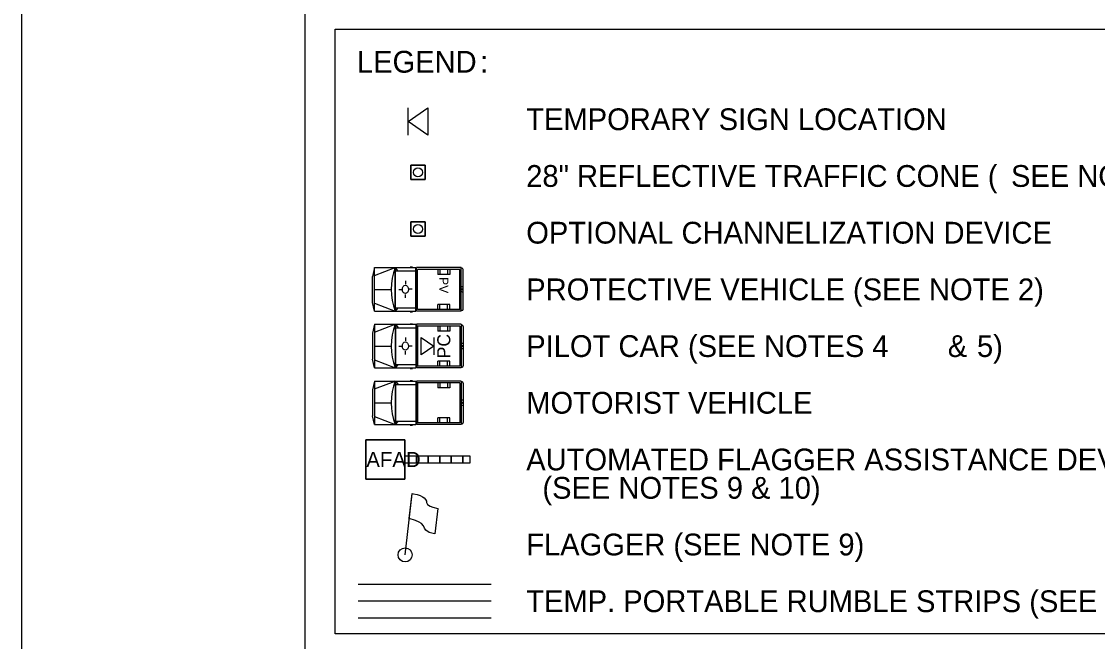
# Model space of a CAD drawing. Extents: x 99999.1 to 100095.7, y 99995 to 100010.7.
# Drawn here: x 99999.062 to 100002.622, y 100001.151 to 100003.2 of the extents above; entities that cross this region are included whole.
import ezdxf

# ---------------------------------------------------------------- set-up
doc = ezdxf.new("R2010")
doc.units = 0
for name, color, linetype in [('SH_GI_PlotLimits', 7, 'Continuous'), ('SH_GI_SheetBorder', 7, 'Continuous'), ('TR_WZ_AFAD', 7, 'Continuous'), ('TR_WZ_FlaggingStation', 7, 'Continuous'), ('TR_WZ_MotoristVehicle', 7, 'Continuous'), ('TR_WZ_PortableSignMountBlk-Org', 7, 'Continuous'), ('TR_WZ_PortableSignMountBlk-Wht', 7, 'Continuous'), ('TR_WZ_ProtectiveVehicle', 7, 'Continuous'), ('TR_WZ_TrafficCone', 7, 'Continuous'), ('TR_WZ_WorkZoneDetails', 7, 'Continuous'), ('TR_WZ_WorkZoneTextCurrent', 7, 'Continuous')]:
    doc.layers.add(name, color=color, linetype=linetype)

msp = doc.modelspace()

# ---------------------------------------------------------------- linework, layer by layer
at = {"layer": 'SH_GI_PlotLimits'}
msp.add_lwpolyline([(99999.0625, 99999.6875), (100016.0625, 99999.6875), (100016.0625, 100010.6875), (99999.0625, 100010.6875)], close=True, dxfattribs=at)
at = {"layer": 'SH_GI_SheetBorder'}
msp.add_line((100000, 100010.375), (100000, 100000), dxfattribs=at)
at = {"layer": 'TR_WZ_AFAD'}
for p, q in [((100000.2009, 100001.6877), (100000.2009, 100001.8173)), ((100000.2009, 100001.8173), (100000.3305, 100001.8173)), ((100000.3305, 100001.8173), (100000.2009, 100001.8173)), ((100000.2009, 100001.8173), (100000.2009, 100001.6877)), ((100000.3305, 100001.8173), (100000.3305, 100001.6877)), ((100000.3305, 100001.7573), (100000.3305, 100001.8173)), ((100000.3689, 100001.7633), (100000.3305, 100001.7633)), ((100000.3305, 100001.7633), (100000.3305, 100001.7573)), ((100000.3305, 100001.7573), (100000.3305, 100001.7525)), ((100000.4073, 100001.7633), (100000.3689, 100001.7633)), ((100000.4457, 100001.7633), (100000.4073, 100001.7633)), ((100000.4073, 100001.7525), (100000.4073, 100001.7633)), ((100000.4073, 100001.7417), (100000.4073, 100001.7525)), ((100000.4841, 100001.7633), (100000.4457, 100001.7633)), ((100000.4457, 100001.7633), (100000.4457, 100001.7525)), ((100000.4457, 100001.7525), (100000.4457, 100001.7417)), ((100000.5225, 100001.7633), (100000.4841, 100001.7633)), ((100000.4841, 100001.7525), (100000.4841, 100001.7633)), ((100000.4841, 100001.7417), (100000.4841, 100001.7525)), ((100000.5225, 100001.7633), (100000.5225, 100001.7525)), ((100000.5225, 100001.7525), (100000.5225, 100001.7417)), ((100000.3689, 100001.7417), (100000.4073, 100001.7417)), ((100000.4073, 100001.7417), (100000.4457, 100001.7417)), ((100000.4457, 100001.7417), (100000.4841, 100001.7417)), ((100000.4841, 100001.7417), (100000.5225, 100001.7417)), ((100000.5225, 100001.7417), (100000.5465, 100001.7417)), ((100000.3305, 100001.6877), (100000.2009, 100001.6877)), ((100000.2009, 100001.6877), (100000.3305, 100001.6877))]:
    msp.add_line(p, q, dxfattribs=at)
for points in [[(100000.3305, 100001.7417), (100000.5465, 100001.7417), (100000.5465, 100001.7633), (100000.3305, 100001.7633)], [(100000.3305, 100001.6877), (100000.3305, 100001.7477), (100000.3305, 100001.7573)], [(100000.3305, 100001.7525), (100000.3305, 100001.7477), (100000.3305, 100001.7417), (100000.3689, 100001.7417)], [(100000.3689, 100001.7417), (100000.3689, 100001.7525), (100000.3689, 100001.7633)], [(100000.3689, 100001.7633), (100000.3689, 100001.7525), (100000.3689, 100001.7417)], [(100000.4073, 100001.7633), (100000.4073, 100001.7525), (100000.4073, 100001.7417)], [(100000.4457, 100001.7417), (100000.4457, 100001.7525), (100000.4457, 100001.7633)], [(100000.4841, 100001.7633), (100000.4841, 100001.7525), (100000.4841, 100001.7417)], [(100000.5225, 100001.7417), (100000.5225, 100001.7525), (100000.5225, 100001.7633)], [(100000.5465, 100001.7417), (100000.5465, 100001.7633), (100000.5225, 100001.7633)]]:
    msp.add_lwpolyline(points, dxfattribs=at)
at = {"layer": 'TR_WZ_FlaggingStation'}
for p, q in [((100000.3314, 100001.4372), (100000.3545, 100001.6394)), ((100000.3451, 100001.5573), (100000.3545, 100001.6397)), ((100000.4394, 100001.5908), (100000.4299, 100001.5065)), ((100000.3451, 100001.5573), (100000.3451, 100001.5573))]:
    msp.add_line(p, q, dxfattribs=at)
for points in [[(100000.3545, 100001.6397), (100000.3586, 100001.6387), (100000.3715, 100001.6363), (100000.3814, 100001.6333), (100000.3884, 100001.6289), (100000.3945, 100001.6255), (100000.3986, 100001.6206), (100000.4017, 100001.6149), (100000.4021, 100001.6105), (100000.4059, 100001.6038), (100000.4137, 100001.5985), (100000.4226, 100001.5947), (100000.4394, 100001.5908)], [(100000.4299, 100001.5065), (100000.424, 100001.5075), (100000.4112, 100001.5108), (100000.4, 100001.5184), (100000.3953, 100001.526), (100000.3925, 100001.5334), (100000.3859, 100001.5412), (100000.378, 100001.5457), (100000.3655, 100001.5508), (100000.3451, 100001.5573)]]:
    msp.add_lwpolyline(points, dxfattribs=at)
msp.add_circle((100000.3314, 100001.4372), 0.0234, dxfattribs=at)
at = {"layer": 'TR_WZ_MotoristVehicle'}
for p, q in [((100000.2305, 100002.1994), (100000.2239, 100002.1704)), ((100000.2305, 100002.1994), (100000.2305, 100002.0554)), ((100000.2305, 100002.1994), (100000.3665, 100002.1994)), ((100000.2305, 100002.1731), (100000.2985, 100002.1994)), ((100000.2985, 100002.1994), (100000.2985, 100002.0554)), ((100000.2998, 100002.1994), (100000.2998, 100002.0554)), ((100000.2998, 100002.1994), (100000.3084, 100002.1883)), ((100000.2998, 100002.1883), (100000.3665, 100002.1883)), ((100000.348, 100002.2015), (100000.3562, 100002.2015)), ((100000.3665, 100002.1994), (100000.3665, 100002.0554)), ((100000.5166, 100002.1994), (100000.3685, 100002.1994)), ((100000.3685, 100002.1994), (100000.3685, 100002.0554)), ((100000.5124, 100002.1937), (100000.3727, 100002.1937)), ((100000.3727, 100002.1937), (100000.3727, 100002.0612)), ((100000.4395, 100002.1937), (100000.4395, 100002.1771)), ((100000.4791, 100002.1771), (100000.4395, 100002.1771)), ((100000.4467, 100002.1937), (100000.4467, 100002.1771)), ((100000.4711, 100002.1937), (100000.4711, 100002.1771)), ((100000.4791, 100002.1937), (100000.4791, 100002.1771)), ((100000.5124, 100002.1937), (100000.5124, 100002.0612)), ((100000.5166, 100002.1994), (100000.5166, 100002.0554)), ((100000.5204, 100002.1971), (100000.5171, 100002.1971)), ((100000.5171, 100002.1971), (100000.5171, 100002.0578)), ((100000.5236, 100002.1927), (100000.5236, 100002.0622)), ((100000.2239, 100002.1704), (100000.2239, 100002.0845)), ((100000.3324, 100002.156), (100000.3324, 100002.1444)), ((100000.5236, 100002.1376), (100000.5171, 100002.1349)), ((100000.2305, 100002.1274), (100000.2852, 100002.1274)), ((100000.3107, 100002.1275), (100000.3198, 100002.1275)), ((100000.3329, 100002.0997), (100000.3327, 100002.1106)), ((100000.3426, 100002.1272), (100000.3426, 100002.1272)), ((100000.3546, 100002.1269), (100000.3439, 100002.1272)), ((100000.5236, 100002.1173), (100000.5171, 100002.12)), ((100000.5218, 100002.1274), (100000.5189, 100002.1274)), ((100000.5204, 100002.1295), (100000.5204, 100002.1254)), ((100000.2305, 100002.0554), (100000.2239, 100002.0845)), ((100000.2305, 100002.0818), (100000.2985, 100002.0554)), ((100000.2998, 100002.0666), (100000.3665, 100002.0666)), ((100000.3069, 100002.0666), (100000.2998, 100002.0554)), ((100000.4395, 100002.0612), (100000.4395, 100002.0777)), ((100000.4791, 100002.0777), (100000.4395, 100002.0777)), ((100000.4467, 100002.0612), (100000.4467, 100002.0777)), ((100000.4711, 100002.0612), (100000.4711, 100002.0777)), ((100000.4791, 100002.0612), (100000.4791, 100002.0777)), ((100000.2305, 100002.0554), (100000.3665, 100002.0554)), ((100000.348, 100002.0534), (100000.3562, 100002.0534)), ((100000.5166, 100002.0554), (100000.3685, 100002.0554)), ((100000.5124, 100002.0612), (100000.3727, 100002.0612)), ((100000.5204, 100002.0578), (100000.5171, 100002.0578)), ((100000.2305, 100002.012), (100000.2239, 100001.9829)), ((100000.2305, 100002.012), (100000.2305, 100001.868)), ((100000.2305, 100002.012), (100000.3665, 100002.012)), ((100000.2305, 100001.9856), (100000.2985, 100002.012)), ((100000.2985, 100002.012), (100000.2985, 100001.868)), ((100000.2998, 100002.012), (100000.2998, 100001.868)), ((100000.2998, 100002.012), (100000.3084, 100002.0008)), ((100000.2998, 100002.0008), (100000.3665, 100002.0008)), ((100000.348, 100002.014), (100000.3562, 100002.014)), ((100000.3665, 100002.012), (100000.3665, 100001.868)), ((100000.5166, 100002.012), (100000.3685, 100002.012)), ((100000.3685, 100002.012), (100000.3685, 100001.868)), ((100000.5124, 100002.0062), (100000.3727, 100002.0062)), ((100000.3727, 100002.0062), (100000.3727, 100001.8737)), ((100000.4395, 100002.0062), (100000.4395, 100001.9897)), ((100000.4467, 100002.0062), (100000.4467, 100001.9897)), ((100000.4711, 100002.0062), (100000.4711, 100001.9897)), ((100000.4791, 100002.0062), (100000.4791, 100001.9897)), ((100000.5124, 100002.0062), (100000.5124, 100001.8737)), ((100000.5166, 100002.012), (100000.5166, 100001.868)), ((100000.5204, 100002.0096), (100000.5171, 100002.0096)), ((100000.5171, 100002.0096), (100000.5171, 100001.8704)), ((100000.5236, 100002.0052), (100000.5236, 100001.8747)), ((100000.2239, 100001.9829), (100000.2239, 100001.8971)), ((100000.4791, 100001.9897), (100000.4395, 100001.9897)), ((100000.2305, 100001.94), (100000.2852, 100001.94)), ((100000.5236, 100001.9501), (100000.5171, 100001.9474)), ((100000.5236, 100001.9298), (100000.5171, 100001.9325)), ((100000.5218, 100001.94), (100000.5189, 100001.94)), ((100000.5204, 100001.942), (100000.5204, 100001.938)), ((100000.2305, 100001.868), (100000.2239, 100001.8971)), ((100000.2305, 100001.8944), (100000.2985, 100001.868)), ((100000.4395, 100001.8737), (100000.4395, 100001.8903)), ((100000.4791, 100001.8903), (100000.4395, 100001.8903)), ((100000.4467, 100001.8737), (100000.4467, 100001.8903)), ((100000.4711, 100001.8737), (100000.4711, 100001.8903)), ((100000.4791, 100001.8737), (100000.4791, 100001.8903)), ((100000.2305, 100001.868), (100000.3665, 100001.868)), ((100000.2998, 100001.8791), (100000.3665, 100001.8791)), ((100000.3069, 100001.8791), (100000.2998, 100001.868)), ((100000.348, 100001.866), (100000.3562, 100001.866)), ((100000.5166, 100001.868), (100000.3685, 100001.868)), ((100000.5124, 100001.8737), (100000.3727, 100001.8737)), ((100000.5204, 100001.8704), (100000.5171, 100001.8704))]:
    msp.add_line(p, q, dxfattribs=at)
for centre, major_axis, start_param, end_param in [((100000.3957, 100002.1274), (0, -0.1511), 4.215667, 5.208926), ((100000.5204, 100002.1927), (0, 0.00439), 4.712389, 6.283185), ((100000.5204, 100002.0622), (0, -0.00439), 0, 1.570796), ((100000.3957, 100001.94), (0, -0.1511), 4.215667, 5.208926), ((100000.5204, 100002.0052), (0, 0.00439), 4.712389, 6.283185), ((100000.5204, 100001.8747), (0, -0.00439), 0, 1.570796)]:
    msp.add_ellipse(centre, major_axis=major_axis, ratio=0.73155, start_param=start_param, end_param=end_param, dxfattribs=at)
for centre, major_axis in [((100000.3324, 100002.1274), (0, 0.0139)), ((100000.5204, 100002.1274), (0, 0.00203)), ((100000.5204, 100001.94), (0, 0.00203))]:
    msp.add_ellipse(centre, major_axis=major_axis, ratio=0.73155, dxfattribs=at)
at = {"layer": 'TR_WZ_PortableSignMountBlk-Org'}
msp.add_line((100000.3414, 100002.8247), (100000.3414, 100002.9147), dxfattribs=at)
msp.add_lwpolyline([(100000.3414, 100002.8696), (100000.406, 100002.9147), (100000.406, 100002.8247)], close=True, dxfattribs=at)
at = {"layer": 'TR_WZ_PortableSignMountBlk-Wht'}
msp.add_line((100000.4259, 100002.1562), (100000.4259, 100002.0986), dxfattribs=at)
msp.add_lwpolyline([(100000.4259, 100002.1274), (100000.3845, 100002.0986), (100000.3845, 100002.1562)], close=True, dxfattribs=at)
at = {"layer": 'TR_WZ_ProtectiveVehicle'}
for p, q in [((100000.2305, 100002.3869), (100000.2239, 100002.3578)), ((100000.2305, 100002.2429), (100000.2305, 100002.3869)), ((100000.2305, 100002.3869), (100000.3665, 100002.3869)), ((100000.2305, 100002.3605), (100000.2985, 100002.3869)), ((100000.2985, 100002.2429), (100000.2985, 100002.3869)), ((100000.2998, 100002.2429), (100000.2998, 100002.3869)), ((100000.3069, 100002.3757), (100000.2998, 100002.3869)), ((100000.348, 100002.3889), (100000.3562, 100002.3889)), ((100000.3665, 100002.2429), (100000.3665, 100002.3869)), ((100000.5166, 100002.3869), (100000.3685, 100002.3869)), ((100000.3685, 100002.2429), (100000.3685, 100002.3869)), ((100000.5166, 100002.2429), (100000.5166, 100002.3869)), ((100000.5204, 100002.3845), (100000.5171, 100002.3845)), ((100000.5171, 100002.2453), (100000.5171, 100002.3845)), ((100000.2239, 100002.272), (100000.2239, 100002.3578)), ((100000.2998, 100002.3757), (100000.3665, 100002.3757)), ((100000.5124, 100002.3811), (100000.3727, 100002.3811)), ((100000.3727, 100002.2486), (100000.3727, 100002.3811)), ((100000.4395, 100002.3811), (100000.4395, 100002.3646)), ((100000.4791, 100002.3646), (100000.4395, 100002.3646)), ((100000.4467, 100002.3811), (100000.4467, 100002.3646)), ((100000.4711, 100002.3811), (100000.4711, 100002.3646)), ((100000.4791, 100002.3811), (100000.4791, 100002.3646)), ((100000.5124, 100002.2486), (100000.5124, 100002.3811)), ((100000.5236, 100002.2497), (100000.5236, 100002.3801)), ((100000.2305, 100002.3149), (100000.2852, 100002.3149)), ((100000.3107, 100002.3148), (100000.3198, 100002.3148)), ((100000.3329, 100002.3426), (100000.3327, 100002.3318)), ((100000.3426, 100002.3151), (100000.3426, 100002.3151)), ((100000.3546, 100002.3154), (100000.3439, 100002.3152)), ((100000.5236, 100002.325), (100000.5171, 100002.3223)), ((100000.5218, 100002.3149), (100000.5189, 100002.3149)), ((100000.5204, 100002.3129), (100000.5204, 100002.3169)), ((100000.3324, 100002.2864), (100000.3324, 100002.298)), ((100000.5236, 100002.3048), (100000.5171, 100002.3075)), ((100000.2305, 100002.2429), (100000.2239, 100002.272)), ((100000.2305, 100002.2693), (100000.2985, 100002.2429)), ((100000.2305, 100002.2429), (100000.3665, 100002.2429)), ((100000.2998, 100002.2429), (100000.3084, 100002.254)), ((100000.2998, 100002.254), (100000.3665, 100002.254)), ((100000.5166, 100002.2429), (100000.3685, 100002.2429)), ((100000.5124, 100002.2486), (100000.3727, 100002.2486)), ((100000.4791, 100002.2652), (100000.4395, 100002.2652)), ((100000.4395, 100002.2486), (100000.4395, 100002.2652)), ((100000.4467, 100002.2486), (100000.4467, 100002.2652)), ((100000.4711, 100002.2486), (100000.4711, 100002.2652)), ((100000.4791, 100002.2486), (100000.4791, 100002.2652)), ((100000.5204, 100002.2453), (100000.5171, 100002.2453)), ((100000.348, 100002.2409), (100000.3562, 100002.2409))]:
    msp.add_line(p, q, dxfattribs=at)
for centre, major_axis, start_param, end_param in [((100000.3957, 100002.3149), (0, -0.1511), 4.215852, 5.209111), ((100000.5204, 100002.3801), (0, 0.00439), 4.712389, 6.283185), ((100000.5204, 100002.2497), (0, -0.00439), 6.283185, 7.853982)]:
    msp.add_ellipse(centre, major_axis=major_axis, ratio=0.73155, start_param=start_param, end_param=end_param, dxfattribs=at)
for centre, major_axis in [((100000.3324, 100002.3149), (0, 0.0139)), ((100000.5204, 100002.3149), (0, 0.00203))]:
    msp.add_ellipse(centre, major_axis=major_axis, ratio=0.73155, dxfattribs=at)
at = {"layer": 'TR_WZ_TrafficCone'}
for points in [[(100000.3497, 100002.7257), (100000.3977, 100002.7257), (100000.3977, 100002.6777), (100000.3497, 100002.6777), (100000.3497, 100002.7257)], [(100000.3497, 100002.6777), (100000.3977, 100002.6777), (100000.3977, 100002.7257), (100000.3497, 100002.7257), (100000.3497, 100002.6777)], [(100000.3497, 100002.5383), (100000.3977, 100002.5383), (100000.3977, 100002.4903), (100000.3497, 100002.4903), (100000.3497, 100002.5383)], [(100000.3497, 100002.4903), (100000.3977, 100002.4903), (100000.3977, 100002.5383), (100000.3497, 100002.5383), (100000.3497, 100002.4903)]]:
    msp.add_lwpolyline(points, dxfattribs=at)
for centre in [(100000.3737, 100002.7017), (100000.3737, 100002.5143)]:
    msp.add_circle(centre, 0.015, dxfattribs=at)
at = {"layer": 'TR_WZ_WorkZoneDetails'}
for p, q in [((100000.6161, 100001.3388), (100000.1761, 100001.3388)), ((100000.6161, 100001.2839), (100000.1761, 100001.2839)), ((100000.6161, 100001.2283), (100000.1761, 100001.2283))]:
    msp.add_line(p, q, dxfattribs=at)
at = {"layer": 'TR_WZ_WorkZoneTextCurrent'}
msp.add_lwpolyline([(100000.1, 100003.1754), (100003.2886, 100003.1754), (100003.2886, 100001.1759), (100000.1, 100001.1759)], close=True, dxfattribs=at)

# ---------------------------------------------------------------- texts
at = {"layer": 'TR_WZ_AFAD'}
msp.add_text('AFAD', height=0.0504, dxfattribs=at).set_placement((100000.203, 100001.7273))
at = {"layer": 'TR_WZ_MotoristVehicle'}
msp.add_text('PC', height=0.0432, rotation=90, dxfattribs=at).set_placement((100000.4809, 100002.0871))
at = {"layer": 'TR_WZ_ProtectiveVehicle'}
msp.add_text('PV', height=0.03006, rotation=270, dxfattribs=at).set_placement((100000.4442, 100002.3557))
at = {"layer": 'TR_WZ_WorkZoneTextCurrent'}
for s, p in [('LEGEND', (100000.172, 100003.0314)), (':', (100000.5795, 100003.0314)), ('TEMPORARY SIGN LOCATION ', (100000.732, 100002.8413)), ('28" REFLECTIVE TRAFFIC CONE (', (100000.732, 100002.6538)), ('SEE NOTE 3', (100002.3354, 100002.6538)), ('OPTIONAL CHANNELIZATION DEVICE', (100000.732, 100002.4663)), ('PROTECTIVE VEHICLE (SEE NOTE 2)', (100000.732, 100002.2789)), ('PILOT CAR (SEE NOTES 4', (100000.732, 100002.0914)), ('&', (100002.1264, 100002.0914)), ('5)', (100002.2229, 100002.0914)), ('MOTORIST VEHICLE', (100000.732, 100001.904)), ('AUTOMATED FLAGGER ASSISTANCE DEVICE', (100000.732, 100001.7165)), ('  (SEE NOTES 9 & 10)', (100000.732, 100001.6228)), ('FLAGGER (SEE NOTE 9)', (100000.732, 100001.4354)), ('TEMP. PORTABLE RUMBLE STRIPS (SEE NOTE 11)', (100000.732, 100001.2479))]:
    msp.add_text(s, height=0.072, rotation=360, dxfattribs=at).set_placement(p)

doc.saveas('drawing.dxf')
